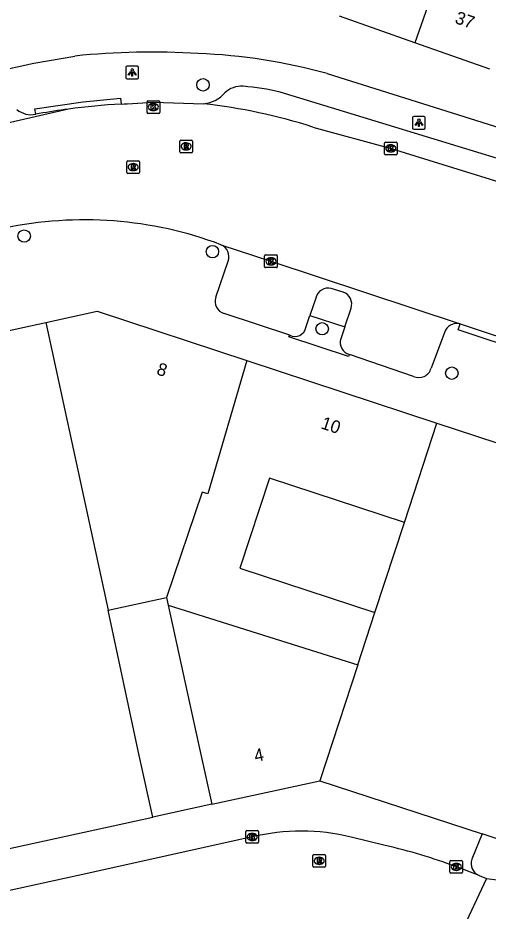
# Model space of a CAD drawing. Extents: x 160557 to 161245, y 385330 to 386505.
# Drawn here: x 160836.9 to 160874.1, y 385868.6 to 385939.3 of the extents above; entities that cross this region are included whole.
import ezdxf

# ---------------------------------------------------------------- set-up
doc = ezdxf.new("R2010")
doc.units = 0
for name, color, linetype in [('IMGEO_Boom', 7, 'Continuous'), ('IMGEO_Kolk', 7, 'Continuous'), ('IMGEO_Lichtpunt', 7, 'Continuous'), ('IMGEO_Pand', 7, 'Continuous'), ('IMGEO_Pand_nummerreeks', 7, 'Continuous'), ('IMGEO_Parkeervlak_open', 7, 'Continuous'), ('IMGEO_Rijbaan_lokaal_gesloten', 7, 'Continuous'), ('IMGEO_Rijbaan_lokaal_open', 7, 'Continuous'), ('IMGEO_Rioolput', 7, 'Continuous'), ('IMGEO_Verkeerseiland_open', 7, 'Continuous'), ('IMGEO_Voetpad_open', 7, 'Continuous')]:
    doc.layers.add(name, color=color, linetype=linetype)

msp = doc.modelspace()

# ---------------------------------------------------------------- linework, layer by layer
at = {"layer": 'IMGEO_Boom'}
for centre in [(160851.565, 385934.003), (160837.424, 385922.041), (160852.311, 385920.806), (160860.985, 385914.7), (160871.235, 385911.19)]:
    msp.add_circle(centre, 0.489, dxfattribs=at)
at = {"layer": 'IMGEO_Kolk'}
for p, q in [((160847.137, 385931.82), (160847.137, 385932.672)), ((160847.212, 385932.746), (160848.064, 385932.746)), ((160848.138, 385932.672), (160848.138, 385931.82)), ((160847.648, 385931.966), (160847.623, 385931.966)), ((160847.625, 385932.526), (160847.65, 385932.526)), ((160848.064, 385931.746), (160847.212, 385931.746)), ((160865.914, 385928.549), (160865.914, 385929.401)), ((160865.989, 385929.475), (160866.841, 385929.475)), ((160866.402, 385929.255), (160866.427, 385929.255)), ((160866.915, 385929.401), (160866.915, 385928.549)), ((160866.841, 385928.475), (160865.989, 385928.475)), ((160866.425, 385928.695), (160866.4, 385928.695)), ((160856.434, 385919.616), (160856.434, 385920.468)), ((160856.509, 385920.542), (160857.361, 385920.542)), ((160856.922, 385920.322), (160856.947, 385920.322)), ((160857.435, 385920.468), (160857.435, 385919.616)), ((160857.361, 385919.542), (160856.509, 385919.542)), ((160856.945, 385919.762), (160856.92, 385919.762)), ((160854.95, 385874.071), (160854.95, 385874.923)), ((160855.025, 385874.997), (160855.877, 385874.997)), ((160855.438, 385874.777), (160855.463, 385874.777)), ((160855.951, 385874.923), (160855.951, 385874.071)), ((160855.877, 385873.997), (160855.025, 385873.997)), ((160855.461, 385874.217), (160855.436, 385874.217)), ((160871.16, 385872.629), (160872.012, 385872.629)), ((160871.085, 385871.703), (160871.085, 385872.555)), ((160871.573, 385872.409), (160871.598, 385872.409)), ((160872.086, 385872.555), (160872.086, 385871.703)), ((160872.012, 385871.629), (160871.16, 385871.629)), ((160871.596, 385871.849), (160871.571, 385871.849))]:
    msp.add_line(p, q, dxfattribs=at)
for points in [[(160847.137, 385931.82), (160847.137, 385932.672)], [(160847.212, 385932.746), (160848.064, 385932.746)], [(160848.138, 385932.672), (160848.138, 385931.82)], [(160847.458, 385932.446), (160847.581, 385932.446), (160847.581, 385932.295), (160847.711, 385932.446), (160847.875, 385932.446), (160847.729, 385932.295), (160847.882, 385932.046), (160847.73, 385932.046), (160847.645, 385932.21), (160847.581, 385932.143), (160847.581, 385932.046), (160847.458, 385932.046), (160847.458, 385932.446)], [(160848.064, 385931.746), (160847.212, 385931.746)], [(160865.914, 385928.549), (160865.914, 385929.401)], [(160865.989, 385929.475), (160866.841, 385929.475)], [(160866.235, 385929.175), (160866.358, 385929.175), (160866.358, 385929.024), (160866.488, 385929.175), (160866.652, 385929.175), (160866.506, 385929.024), (160866.659, 385928.775), (160866.507, 385928.775), (160866.422, 385928.939), (160866.358, 385928.872), (160866.358, 385928.775), (160866.235, 385928.775), (160866.235, 385929.175)], [(160866.915, 385929.401), (160866.915, 385928.549)], [(160866.841, 385928.475), (160865.989, 385928.475)], [(160856.434, 385919.616), (160856.434, 385920.468)], [(160856.509, 385920.542), (160857.361, 385920.542)], [(160856.755, 385920.242), (160856.878, 385920.242), (160856.878, 385920.091), (160857.008, 385920.242), (160857.172, 385920.242), (160857.026, 385920.091), (160857.179, 385919.842), (160857.027, 385919.842), (160856.942, 385920.006), (160856.878, 385919.939), (160856.878, 385919.842), (160856.755, 385919.842), (160856.755, 385920.242)], [(160857.435, 385920.468), (160857.435, 385919.616)], [(160857.361, 385919.542), (160856.509, 385919.542)], [(160854.95, 385874.071), (160854.95, 385874.923)], [(160855.025, 385874.997), (160855.877, 385874.997)], [(160855.951, 385874.923), (160855.951, 385874.071)], [(160855.877, 385873.997), (160855.025, 385873.997)], [(160855.271, 385874.697), (160855.394, 385874.697), (160855.394, 385874.546), (160855.524, 385874.697), (160855.688, 385874.697), (160855.542, 385874.546), (160855.695, 385874.297), (160855.543, 385874.297), (160855.458, 385874.461), (160855.394, 385874.394), (160855.394, 385874.297), (160855.271, 385874.297), (160855.271, 385874.697)], [(160871.16, 385872.629), (160872.012, 385872.629)], [(160871.085, 385871.703), (160871.085, 385872.555)], [(160871.406, 385872.329), (160871.529, 385872.329), (160871.529, 385872.178), (160871.659, 385872.329), (160871.823, 385872.329), (160871.677, 385872.178), (160871.83, 385871.929), (160871.678, 385871.929), (160871.593, 385872.093), (160871.529, 385872.026), (160871.529, 385871.929), (160871.406, 385871.929), (160871.406, 385872.329)], [(160872.086, 385872.555), (160872.086, 385871.703)], [(160872.012, 385871.629), (160871.16, 385871.629)]]:
    msp.add_lwpolyline(points, dxfattribs=at)
for centre, start, end in [((160847.214, 385932.67), 91.55205, 178.44795), ((160847.214, 385932.67), 91.55205, 178.44795), ((160848.062, 385932.67), 1.55205, 88.44795), ((160848.062, 385932.67), 1.55205, 88.44795), ((160847.214, 385931.822), 181.55205, 268.44795), ((160847.214, 385931.822), 181.55205, 268.44795), ((160848.062, 385931.822), 271.55205, 358.44795), ((160848.062, 385931.822), 271.55205, 358.44795), ((160865.991, 385929.399), 91.55205, 178.44795), ((160865.991, 385929.399), 91.55205, 178.44795), ((160866.839, 385929.399), 1.55205, 88.44795), ((160866.839, 385929.399), 1.55205, 88.44795), ((160865.991, 385928.551), 181.55205, 268.44795), ((160865.991, 385928.551), 181.55205, 268.44795), ((160866.839, 385928.551), 271.55205, 358.44795), ((160866.839, 385928.551), 271.55205, 358.44795), ((160856.511, 385920.466), 91.55205, 178.44795), ((160856.511, 385920.466), 91.55205, 178.44795), ((160857.359, 385920.466), 1.55205, 88.44795), ((160857.359, 385920.466), 1.55205, 88.44795), ((160856.511, 385919.618), 181.55205, 268.44795), ((160856.511, 385919.618), 181.55205, 268.44795), ((160857.359, 385919.618), 271.55205, 358.44795), ((160857.359, 385919.618), 271.55205, 358.44795), ((160855.027, 385874.921), 91.55205, 178.44795), ((160855.027, 385874.921), 91.55205, 178.44795), ((160855.875, 385874.921), 1.55205, 88.44795), ((160855.875, 385874.921), 1.55205, 88.44795), ((160855.027, 385874.073), 181.55205, 268.44795), ((160855.027, 385874.073), 181.55205, 268.44795), ((160855.875, 385874.073), 271.55205, 358.44795), ((160855.875, 385874.073), 271.55205, 358.44795), ((160871.162, 385872.553), 91.55205, 178.44795), ((160871.162, 385872.553), 91.55205, 178.44795), ((160872.01, 385872.553), 1.55205, 88.44795), ((160872.01, 385872.553), 1.55205, 88.44795), ((160871.162, 385871.705), 181.55205, 268.44795), ((160871.162, 385871.705), 181.55205, 268.44795), ((160872.01, 385871.705), 271.55205, 358.44795), ((160872.01, 385871.705), 271.55205, 358.44795)]:
    msp.add_arc(centre, 0.0765, start, end, dxfattribs=at)
for centre, major_axis, ratio, start_param, end_param in [((160847.624, 385932.246), (-0.387, 0.002), 0.722429, 4.712389, 7.853982), ((160847.649, 385932.246), (-0.39, 0.002), 0.717154, 1.570796, 4.712389), ((160866.401, 385928.975), (-0.387, 0.002), 0.722429, 4.712389, 7.853982), ((160866.426, 385928.975), (-0.39, 0.002), 0.717154, 1.570796, 4.712389), ((160856.921, 385920.042), (-0.387, 0.002), 0.722429, 4.712389, 7.853982), ((160856.946, 385920.042), (-0.39, 0.002), 0.717154, 1.570796, 4.712389), ((160855.437, 385874.497), (-0.387, 0.002), 0.722429, 4.712389, 7.853982), ((160855.462, 385874.497), (-0.39, 0.002), 0.717154, 1.570796, 4.712389), ((160871.572, 385872.129), (-0.387, 0.002), 0.722429, 4.712389, 7.853982), ((160871.597, 385872.129), (-0.39, 0.002), 0.717154, 1.570796, 4.712389)]:
    msp.add_ellipse(centre, major_axis=major_axis, ratio=ratio, start_param=start_param, end_param=end_param, dxfattribs=at)
at = {"layer": 'IMGEO_Lichtpunt'}
for p, q in [((160845.472, 385935.387), (160845.472, 385934.58)), ((160845.472, 385935.387), (160845.472, 385934.58)), ((160846.374, 385935.482), (160845.566, 385935.482)), ((160846.374, 385935.482), (160845.566, 385935.482)), ((160846.468, 385934.58), (160846.468, 385935.387)), ((160846.468, 385934.58), (160846.468, 385935.387)), ((160845.566, 385934.486), (160846.374, 385934.486)), ((160845.566, 385934.486), (160846.374, 385934.486)), ((160868.136, 385931.409), (160868.136, 385930.602)), ((160868.136, 385931.409), (160868.136, 385930.602)), ((160869.038, 385931.504), (160868.23, 385931.504)), ((160869.038, 385931.504), (160868.23, 385931.504)), ((160869.132, 385930.602), (160869.132, 385931.409)), ((160869.132, 385930.602), (160869.132, 385931.409)), ((160868.23, 385930.508), (160869.038, 385930.508)), ((160868.23, 385930.508), (160869.038, 385930.508))]:
    msp.add_line(p, q, dxfattribs=at)
for points in [[(160845.846, 385935.051), (160845.885, 385935.023), (160845.697, 385934.761), (160845.659, 385934.788), (160845.846, 385935.051)], [(160845.948, 385935.003), (160845.995, 385935.003), (160845.995, 385934.681), (160845.948, 385934.681), (160845.948, 385935.003)], [(160846.058, 385935.023), (160846.096, 385935.05), (160846.283, 385934.788), (160846.244, 385934.76), (160846.058, 385935.023)], [(160868.51, 385931.073), (160868.549, 385931.045), (160868.361, 385930.783), (160868.323, 385930.81), (160868.51, 385931.073)], [(160868.612, 385931.025), (160868.659, 385931.025), (160868.659, 385930.703), (160868.612, 385930.703), (160868.612, 385931.025)], [(160868.722, 385931.045), (160868.76, 385931.072), (160868.947, 385930.81), (160868.908, 385930.782), (160868.722, 385931.045)]]:
    msp.add_lwpolyline(points, dxfattribs=at)
for centre in [(160845.971, 385935.185), (160868.635, 385931.207)]:
    msp.add_circle(centre, 0.0994, dxfattribs=at)
for centre, start, end in [((160845.566, 385935.387), 90, 180), ((160845.566, 385935.387), 90, 180), ((160846.374, 385935.387), 0, 90), ((160846.374, 385935.387), 0, 90), ((160845.566, 385934.58), 180, 270), ((160845.566, 385934.58), 180, 270), ((160846.374, 385934.58), 270, 0), ((160846.374, 385934.58), 270, 360), ((160868.23, 385931.409), 90, 180), ((160868.23, 385931.409), 90, 180), ((160869.038, 385931.409), 0, 90), ((160869.038, 385931.409), 0, 90), ((160868.23, 385930.602), 180, 270), ((160868.23, 385930.602), 180, 270), ((160869.038, 385930.602), 270, 0), ((160869.038, 385930.602), 270, 360)]:
    msp.add_arc(centre, 0.0946, start, end, dxfattribs=at)
at = {"layer": 'IMGEO_Pand'}
for points in [[(160871.187, 385945.521), (160868.3, 385937.337)], [(160868.3, 385937.337), (160862.365, 385939.432)], [(160874.235, 385935.243), (160868.3, 385937.337)], [(160839.147, 385915.209), (160843.195, 385916.09), (160855.021, 385912.197)], [(160824.466, 385912.014), (160839.147, 385915.209)], [(160839.147, 385915.209), (160844.062, 385892.433)], [(160855.021, 385912.197), (160851.934, 385901.64), (160851.486, 385901.786), (160848.675, 385893.441)], [(160855.021, 385912.197), (160870.059, 385907.246)], [(160867.486, 385899.383), (160870.059, 385907.246)], [(160870.059, 385907.246), (160887.405, 385901.535), (160887.221, 385900.976), (160890.467, 385899.91), (160890.636, 385900.424), (160891.506, 385900.139), (160891.349, 385899.659), (160893.159, 385899.065), (160893.43, 385899.454), (160893.721, 385899.359)], [(160867.486, 385899.383), (160856.815, 385902.876), (160854.484, 385895.754), (160865.156, 385892.262)], [(160865.156, 385892.262), (160867.486, 385899.383)], [(160844.062, 385892.433), (160848.675, 385893.441)], [(160848.675, 385893.441), (160848.808, 385892.831)], [(160847.594, 385876.059), (160846.525, 385880.944), (160844.062, 385892.433)], [(160848.808, 385892.831), (160863.802, 385888.125)], [(160848.808, 385892.831), (160851.185, 385881.963), (160852.254, 385877.078)], [(160863.802, 385888.125), (160865.156, 385892.262)], [(160863.802, 385888.125), (160860.8, 385878.948)], [(160852.254, 385877.078), (160860.8, 385878.948)], [(160860.8, 385878.948), (160873.636, 385874.736)], [(160832.965, 385872.859), (160847.594, 385876.059)], [(160878.094, 385873.273), (160873.636, 385874.736)]]:
    msp.add_lwpolyline(points, dxfattribs=at)
at = {"layer": 'IMGEO_Parkeervlak_open'}
for points in [[(160862.651, 385917.608), (160861.701, 385917.9)], [(160860.481, 385917.123), (160860.005, 385915.743)], [(160859.684, 385914.813), (160860.005, 385915.743)], [(160862.772, 385914.863), (160863.27, 385916.327)], [(160862.772, 385914.863), (160862.45, 385913.917)], [(160852.254, 385877.078), (160847.594, 385876.059)]]:
    msp.add_lwpolyline(points, dxfattribs=at)
for centre, radius, start, end in [((160861.476, 385916.908), 1.018, 77.20571, 167.77921), ((160862.303, 385916.65), 1.02, 341.54882, 70.03235), ((160858.847, 385914.941), 0.847, 240.37439, 351.28667), ((160863.438, 385913.643), 1.026, 164.51399, 252.67488)]:
    msp.add_arc(centre, radius, start, end, dxfattribs=at)
at = {"layer": 'IMGEO_Rijbaan_lokaal_gesloten'}
for points in [[(160840.924, 385932.085), (160816.018, 385926.352), (160787.915, 385920.21), (160763.809, 385914.925), (160759.912, 385914.039), (160756.492, 385913.428), (160750.518, 385912.437), (160745.49, 385911.828)], [(160845.083, 385932.48), (160845.324, 385932.494), (160845.565, 385932.507), (160847.643, 385932.641), (160851.615, 385932.511)], [(160860.248, 385930.666), (160866.444, 385928.966), (160880.216, 385924.684)], [(160852.978, 385921.354), (160856.936, 385920.042), (160871.904, 385915.104)], [(160871.904, 385915.104), (160877.365, 385913.283)]]:
    msp.add_lwpolyline(points, dxfattribs=at)
for centre, radius, start, end in [((160848.627, 385873.069), 59.517, 93.41407, 97.43669), ((160846.543, 385887.659), 45.138, 72.32463, 83.54841), ((160842.189, 385892.775), 30.548, 69.3173, 101.99319)]:
    msp.add_arc(centre, radius, start, end, dxfattribs=at)
at = {"layer": 'IMGEO_Rijbaan_lokaal_open'}
for points in [[(160855.448, 385874.495), (160842.527, 385871.618), (160823.141, 385867.378), (160802.504, 385862.88)], [(160865.968, 385873.83), (160863.274, 385874.484)], [(160873.385, 385871.446), (160871.559, 385872.147)], [(160873.972, 385871.217), (160871.183, 385865.245)], [(160873.385, 385871.446), (160873.972, 385871.217)]]:
    msp.add_lwpolyline(points, dxfattribs=at)
for centre, radius, start, end in [((160859.339, 385858.488), 16.473, 76.1779, 103.66103), ((160855.155, 385827.782), 47.301, 69.70864, 76.78573)]:
    msp.add_arc(centre, radius, start, end, dxfattribs=at)
at = {"layer": 'IMGEO_Rioolput'}
for p, q in [((160849.725, 385928.706), (160849.725, 385929.558)), ((160849.8, 385929.632), (160850.652, 385929.632)), ((160850.213, 385929.412), (160850.238, 385929.412)), ((160850.726, 385929.558), (160850.726, 385928.706)), ((160850.652, 385928.632), (160849.8, 385928.632)), ((160850.236, 385928.852), (160850.211, 385928.852)), ((160845.542, 385927.07), (160845.542, 385927.922)), ((160845.617, 385927.996), (160846.469, 385927.996)), ((160846.03, 385927.776), (160846.055, 385927.776)), ((160846.543, 385927.922), (160846.543, 385927.07)), ((160846.053, 385927.216), (160846.028, 385927.216)), ((160846.469, 385926.996), (160845.617, 385926.996)), ((160860.251, 385872.179), (160860.251, 385873.031)), ((160860.326, 385873.105), (160861.178, 385873.105)), ((160860.739, 385872.885), (160860.764, 385872.885)), ((160861.252, 385873.031), (160861.252, 385872.179)), ((160861.178, 385872.105), (160860.326, 385872.105)), ((160860.762, 385872.325), (160860.737, 385872.325))]:
    msp.add_line(p, q, dxfattribs=at)
for points in [[(160849.725, 385928.706), (160849.725, 385929.558)], [(160849.8, 385929.632), (160850.652, 385929.632)], [(160850.314, 385929.33), (160850.062, 385929.332), (160850.062, 385928.932)], [(160850.24, 385929.251), (160850.186, 385929.251), (160850.186, 385929.17)], [(160850.186, 385929.17), (160850.238, 385929.17)], [(160850.726, 385929.558), (160850.726, 385928.706)], [(160850.652, 385928.632), (160849.8, 385928.632)], [(160850.062, 385928.932), (160850.186, 385928.932), (160850.186, 385929.094), (160850.197, 385929.094)], [(160850.244, 385929.065), (160850.315, 385928.932), (160850.455, 385928.932), (160850.39, 385929.058)], [(160845.542, 385927.07), (160845.542, 385927.922)], [(160845.617, 385927.996), (160846.469, 385927.996)], [(160846.543, 385927.922), (160846.543, 385927.07)], [(160846.131, 385927.694), (160845.879, 385927.696), (160845.879, 385927.296)], [(160845.879, 385927.296), (160846.003, 385927.296), (160846.003, 385927.458), (160846.014, 385927.458)], [(160846.057, 385927.615), (160846.003, 385927.615), (160846.003, 385927.534)], [(160846.003, 385927.534), (160846.055, 385927.534)], [(160846.061, 385927.429), (160846.132, 385927.296), (160846.272, 385927.296), (160846.207, 385927.422)], [(160846.469, 385926.996), (160845.617, 385926.996)], [(160860.251, 385872.179), (160860.251, 385873.031)], [(160860.326, 385873.105), (160861.178, 385873.105)], [(160860.84, 385872.803), (160860.588, 385872.805), (160860.588, 385872.405)], [(160860.766, 385872.724), (160860.712, 385872.724), (160860.712, 385872.643)], [(160860.712, 385872.643), (160860.764, 385872.643)], [(160861.252, 385873.031), (160861.252, 385872.179)], [(160861.178, 385872.105), (160860.326, 385872.105)], [(160860.588, 385872.405), (160860.712, 385872.405), (160860.712, 385872.567), (160860.723, 385872.567)], [(160860.77, 385872.538), (160860.841, 385872.405), (160860.981, 385872.405), (160860.916, 385872.531)]]:
    msp.add_lwpolyline(points, dxfattribs=at)
for centre, radius, start, end in [((160849.802, 385929.556), 0.0765, 91.55205, 178.44795), ((160849.802, 385929.556), 0.0765, 91.55205, 178.44795), ((160850.222, 385929.359), 0.19, 274.7715, 282.96867), ((160850.246, 385929.155), 0.0964, 77.00612, 93.18647), ((160850.26, 385929.212), 0.0378, 276.66336, 79.67722), ((160850.313, 385929.22), 0.109, 350.36119, 89.41601), ((160850.311, 385929.22), 0.112, 277.58423, 350.98172), ((160850.65, 385929.556), 0.0765, 1.55205, 88.44795), ((160850.65, 385929.556), 0.0765, 1.55205, 88.44795), ((160849.802, 385928.708), 0.0765, 181.55205, 268.44795), ((160849.802, 385928.708), 0.0765, 181.55205, 268.44795), ((160850.196, 385929.041), 0.0533, 26.02933, 88.69889), ((160850.295, 385929.005), 0.108, 29.51342, 73.79051), ((160850.65, 385928.708), 0.0765, 271.55205, 358.44795), ((160850.65, 385928.708), 0.0765, 271.55205, 358.44795), ((160845.619, 385927.92), 0.0765, 91.55205, 178.44795), ((160845.619, 385927.92), 0.0765, 91.55205, 178.44795), ((160846.467, 385927.92), 0.0765, 1.55205, 88.44795), ((160846.467, 385927.92), 0.0765, 1.55205, 88.44795), ((160845.619, 385927.072), 0.0765, 181.55205, 268.44795), ((160845.619, 385927.072), 0.0765, 181.55205, 268.44795), ((160846.013, 385927.405), 0.0533, 26.02933, 88.69889), ((160846.039, 385927.723), 0.19, 274.7715, 282.96867), ((160846.063, 385927.519), 0.0964, 77.00612, 93.18647), ((160846.077, 385927.576), 0.0378, 276.66336, 79.67722), ((160846.13, 385927.584), 0.109, 350.36119, 89.41601), ((160846.128, 385927.584), 0.112, 277.58423, 350.98172), ((160846.112, 385927.369), 0.108, 29.51342, 73.79051), ((160846.467, 385927.072), 0.0765, 271.55205, 358.44795), ((160846.467, 385927.072), 0.0765, 271.55205, 358.44795), ((160860.328, 385873.029), 0.0765, 91.55205, 178.44795), ((160860.328, 385873.029), 0.0765, 91.55205, 178.44795), ((160860.748, 385872.832), 0.19, 274.7715, 282.96867), ((160860.772, 385872.628), 0.0964, 77.00612, 93.18647), ((160860.786, 385872.685), 0.0378, 276.66336, 79.67722), ((160860.839, 385872.693), 0.109, 350.36119, 89.41601), ((160860.837, 385872.693), 0.112, 277.58423, 350.98172), ((160860.821, 385872.478), 0.108, 29.51342, 73.79051), ((160861.176, 385873.029), 0.0765, 1.55205, 88.44795), ((160861.176, 385873.029), 0.0765, 1.55205, 88.44795), ((160860.328, 385872.181), 0.0765, 181.55205, 268.44795), ((160860.328, 385872.181), 0.0765, 181.55205, 268.44795), ((160860.722, 385872.514), 0.0533, 26.02933, 88.69889), ((160861.176, 385872.181), 0.0765, 271.55205, 358.44795), ((160861.176, 385872.181), 0.0765, 271.55205, 358.44795)]:
    msp.add_arc(centre, radius, start, end, dxfattribs=at)
for centre, major_axis, ratio, start_param, end_param in [((160850.212, 385929.132), (-0.387, 0.002), 0.722429, 4.712389, 7.853982), ((160850.237, 385929.132), (-0.39, 0.002), 0.717154, 1.570796, 4.712389), ((160846.029, 385927.496), (-0.387, 0.002), 0.722429, 4.712389, 7.853982), ((160846.054, 385927.496), (-0.39, 0.002), 0.717154, 1.570796, 4.712389), ((160860.738, 385872.605), (-0.387, 0.002), 0.722429, 4.712389, 7.853982), ((160860.763, 385872.605), (-0.39, 0.002), 0.717154, 1.570796, 4.712389)]:
    msp.add_ellipse(centre, major_axis=major_axis, ratio=ratio, start_param=start_param, end_param=end_param, dxfattribs=at)
at = {"layer": 'IMGEO_Verkeerseiland_open'}
msp.add_lwpolyline([(160860.005, 385915.743), (160862.772, 385914.863)], dxfattribs=at)
at = {"layer": 'IMGEO_Voetpad_open'}
for points in [[(160791.225, 385925.374), (160838.197, 385935.721), (160841.431, 385936.281)], [(160861.372, 385934.889), (160883.981, 385927.769)], [(160877.339, 385927.4), (160857.671, 385933.434)], [(160838.334, 385931.674), (160838.272, 385932.109), (160842.087, 385932.647), (160845.038, 385932.957), (160845.083, 385932.48)], [(160838.608, 385931.728), (160838.334, 385931.674)], [(160852.581, 385917.199), (160853.546, 385920.046)], [(160858.428, 385914.205), (160853.231, 385915.921)], [(160877.365, 385913.283), (160877.207, 385912.809), (160871.746, 385914.63), (160871.904, 385915.104)], [(160870.643, 385914.405), (160869.596, 385911.575)], [(160863.133, 385912.664), (160863.065, 385912.514), (160858.347, 385914.06), (160858.428, 385914.205)], [(160868.21, 385910.93), (160863.133, 385912.664)], [(160873.636, 385874.736), (160872.822, 385872.731)], [(160873.972, 385871.217), (160881.233, 385870.281)]]:
    msp.add_lwpolyline(points, dxfattribs=at)
for centre, radius, start, end in [((160847.499, 385878.423), 58.175, 86.37548, 95.98751), ((160849.474, 385892.163), 44.352, 74.43891, 87.79943), ((160851.42, 385934.925), 2.422, 274.61341, 320.20977), ((160854.621, 385931.902), 1.991, 86.71211, 132.2957), ((160853.273, 385914.794), 19.152, 76.72283, 85.62064), ((160837.99, 385933.454), 1.813, 230.7524, 280.94015), ((160846.91, 385885.56), 46.908, 97.3316, 100.19418), ((160852.598, 385920.411), 1.016, 338.92745, 68.01841), ((160853.474, 385916.849), 0.959, 158.58298, 255.33345), ((160871.659, 385914.059), 1.073, 76.79931, 161.20182), ((160868.621, 385911.859), 1.016, 246.15517, 343.75635), ((160873.81, 385872.398), 1.043, 161.39121, 245.92834)]:
    msp.add_arc(centre, radius, start, end, dxfattribs=at)

# ---------------------------------------------------------------- texts
at = {"layer": 'IMGEO_Pand_nummerreeks'}
for s, rotation, p in [('37', 340.56188, (160871.409, 385938.912)), ('8', 341.77721, (160847.825, 385911.113)), ('10', 341.77994, (160860.819, 385906.835)), ('4', 12.34651, (160855.719, 385880.416))]:
    msp.add_text(s, height=1, rotation=rotation, dxfattribs=at).set_placement(p)

doc.saveas('drawing.dxf')
